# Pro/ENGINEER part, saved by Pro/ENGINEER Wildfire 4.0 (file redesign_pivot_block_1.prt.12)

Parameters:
  METRIC = "NO"

Other parameters: PITCH, DRILL_POINT_ANGLE, DRILL_DEPTH, DRILL_DIAMETER, THREAD_DIAMETER, THREADS_PER_INCH, THREAD_DEPTH, THREAD_LENGTH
